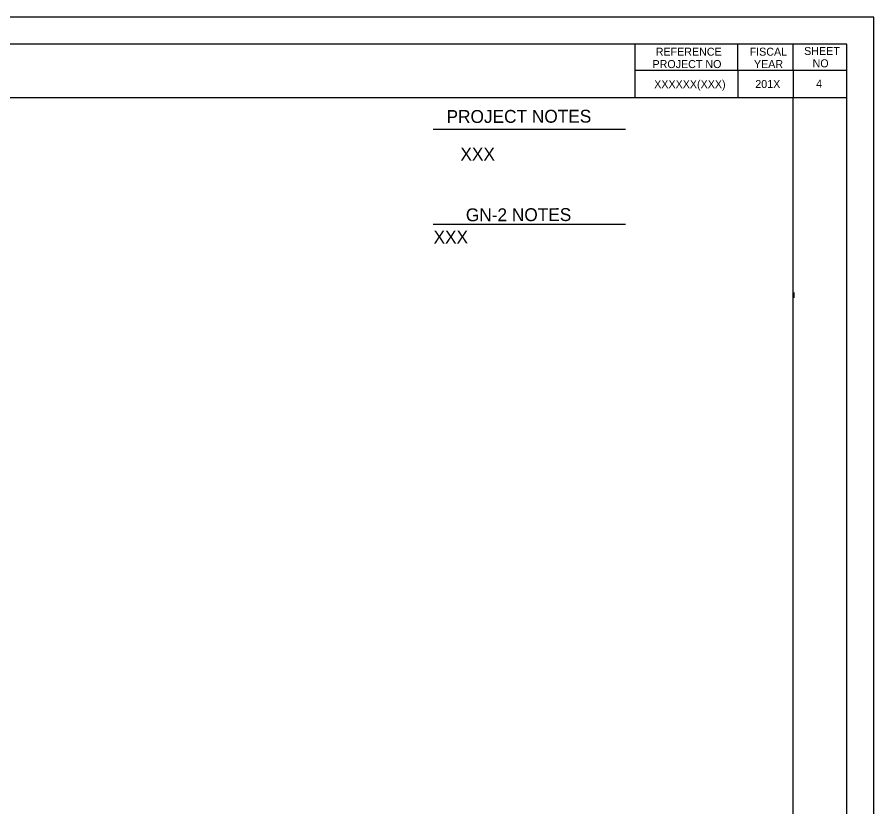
# Model space of a CAD drawing. Extents: x -12822 to 16384, y -6351 to 1913.
# Drawn here: x 3489 to 5083, y 445 to 1913 of the extents above; entities that cross this region are included whole.
import ezdxf

# ---------------------------------------------------------------- set-up
doc = ezdxf.new("R2010")
doc.units = 0
for name, color, linetype in [('2', 7, 'Continuous'), ('ANNO-SHT', 7, 'Continuous'), ('AXIS', 7, 'Continuous'), ('CL-CNST', 7, 'Continuous'), ('Level 37', 7, 'Continuous'), ('Level 6', 7, 'Continuous'), ('Level 62', 7, 'Continuous'), ('SHT-BDR', 7, 'Continuous'), ('SHT-BNDRY', 7, 'Continuous')]:
    doc.layers.add(name, color=color, linetype=linetype)

msp = doc.modelspace()

# ---------------------------------------------------------------- linework, layer by layer
at = {"layer": '2'}
msp.add_lwpolyline([(4933.8, 1401.3), (4933.7, 1391.3)], dxfattribs=at)
msp.add_lwpolyline([(4933.8, 1401.3), (4933.7, 1391.3)], dxfattribs=at)
at = {"layer": 'AXIS'}
msp.add_line((4932.7, 963.4), (4932.7, 963.5), dxfattribs=at)
at = {"layer": 'CL-CNST'}
for p, q in [((4262.8, 1705), (4620.6, 1705)), ((4262.8, 1528.3), (4620.6, 1528.3))]:
    msp.add_line(p, q, dxfattribs=at)
at = {"layer": 'Level 6'}
for p, q in [((4638.1, 1863.4), (4638.1, 1763.5)), ((4829.8, 1813.4), (4829.8, 1863.4)), ((4932.7, 1814.7), (4932.7, 1863.4)), ((5032.7, 1814), (4638.1, 1814)), ((4829.8, 1813.4), (4829.8, 1763.5)), ((4932.7, 1814.7), (4932.7, 1763.5)), ((5032.7, 1763.5), (4650.2, 1763.5))]:
    msp.add_line(p, q, dxfattribs=at)
at = {"layer": 'Level 62'}
msp.add_lwpolyline([(1682.7, -286.6), (5082.7, -286.6), (5082.7, 1913.4), (1682.7, 1913.4)], close=True, dxfattribs=at)
at = {"layer": 'SHT-BDR'}
msp.add_lwpolyline([(1932.6, -136.5), (4932.7, -136.5), (4932.7, 1763.5), (1932.6, 1763.5)], close=True, dxfattribs=at)
at = {"layer": 'SHT-BNDRY'}
msp.add_lwpolyline([(1807.7, -236.6), (5032.7, -236.6), (5032.7, 1863.4), (1807.7, 1863.4)], close=True, dxfattribs=at)

# ---------------------------------------------------------------- texts
at = {"layer": 'ANNO-SHT'}
for s, height, p in [('XXXXXX(XXX)', 14.899, (4674, 1781.3)), ('201X', 14.9, (4862.1, 1781.6)), ('4', 14.9, (4975.3, 1782.2))]:
    msp.add_text(s, height=height, rotation=360, dxfattribs=at).set_placement(p)
at = {"layer": 'Level 37'}
for s, p in [('PROJECT NOTES', (4287.8, 1716.5)), ('XXX', (4313.6, 1646.6)), ('GN-2 NOTES', (4323.7, 1533.7)), ('XXX', (4263.6, 1492.3))]:
    msp.add_text(s, height=24, rotation=0.1539, dxfattribs=at).set_placement(p)
at = {"layer": 'Level 6'}
for s, p in [('REFERENCE', (4676.9, 1841.7)), ('FISCAL', (4851.6, 1841.7)), ('SHEET', (4953, 1843.1)), ('PROJECT NO', (4670.9, 1818.7)), ('YEAR', (4859.6, 1818.7)), ('NO', (4968.7, 1820.1))]:
    msp.add_text(s, height=14.88, rotation=360, dxfattribs=at).set_placement(p)

doc.saveas('drawing.dxf')
